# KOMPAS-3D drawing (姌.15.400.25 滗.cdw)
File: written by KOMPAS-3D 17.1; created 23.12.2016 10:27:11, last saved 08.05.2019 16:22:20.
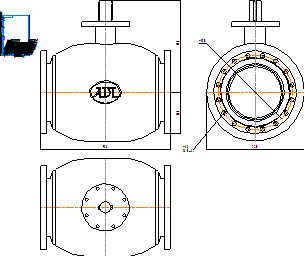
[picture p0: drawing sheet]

Sheet 1: A4, portrait

Title block, sheet 1: material: Внимание! Данный продукт является объектом авторского права ООО «Торговый Дом АДЛ». / Запрещается изменение, копирование, распространение / (в том числе путем копирования на другие сайты и ресурсы в Интернете) / или любое иное использование информации и объектов без предварительного / согласия правообладателя (ООО «Торговый Дом АДЛ»).; mass: 1,3; sheets: 1; organisation: ООО "Торговый дом АДЛ"; sheet format: A4; stored path: C:\Users\tra\Desktop\2д чертежи\Шаровые краны БИВАЛ\КШ_Бивал_серия_14_15\KOMPAS_2D\КШ.15.400.25 фф.cdw

Views: Вид 1, Проекционный вид 2, Проекционный вид 3
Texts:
  Klimkovich
  ADL
Dimensions and other numbers on the sheet: 956; 305; 673; 720; 550; 33; 16 Отв.; 1:1; 1; 1,3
